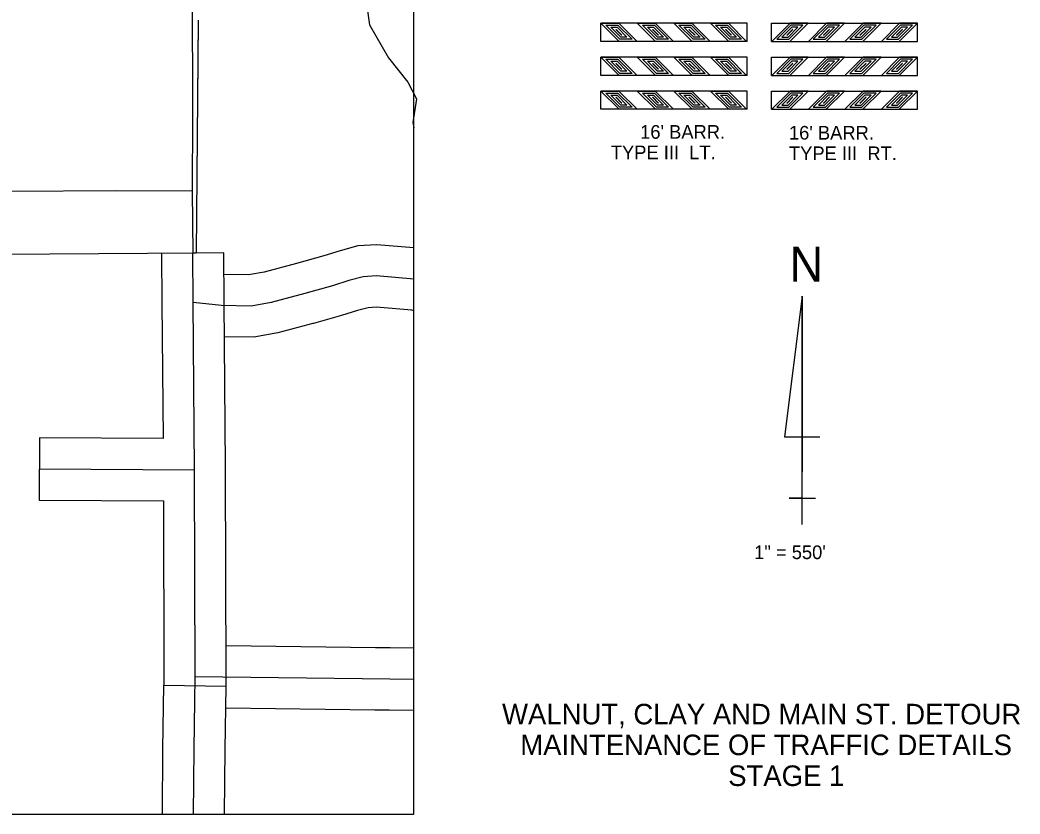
# Model space of a CAD drawing. Extents: x 988392 to 996681, y 1838707 to 1844440.
# Drawn here: x 994176 to 996584, y 1838707 to 1840620 of the extents above; entities that cross this region are included whole.
import ezdxf

# ---------------------------------------------------------------- set-up
doc = ezdxf.new("R2010")
doc.units = 0
for name, color, linetype in [('3', 7, 'Continuous'), ('63', 7, 'Continuous'), ('8', 7, 'Continuous'), ('G-ANNO-TEXT', 7, 'Continuous'), ('G-Border-Sheet', 7, 'Continuous'), ('Level 31', 7, 'Continuous'), ('Level 33', 7, 'Continuous'), ('Level 35', 7, 'Continuous'), ('Level 45', 7, 'Continuous'), ('Level 6', 7, 'Continuous')]:
    doc.layers.add(name, color=color, linetype=linetype)

msp = doc.modelspace()

# ---------------------------------------------------------------- linework, layer by layer
at = {"layer": '3'}
for p, q in [((995927, 1840612.6), (995574.8, 1840612.6)), ((995574.8, 1840568.4), (995574.8, 1840612.6)), ((995927, 1840568.4), (995927, 1840612.6)), ((995985.8, 1840612.6), (996337.9, 1840612.6)), ((995985.8, 1840568.4), (995985.8, 1840612.6)), ((996337.9, 1840568.4), (996337.9, 1840612.6)), ((995575.1, 1840568.5), (995574.8, 1840568.8)), ((995927, 1840568.4), (995574.8, 1840568.4)), ((995985.8, 1840568.4), (996337.9, 1840568.4)), ((996337.7, 1840568.5), (996337.9, 1840568.8)), ((995927, 1840530.6), (995574.8, 1840530.6)), ((995574.8, 1840486.5), (995574.8, 1840530.6)), ((995574.8, 1840486.5), (995574.8, 1840530.6)), ((995927, 1840486.5), (995927, 1840530.6)), ((995985.8, 1840530.6), (996337.9, 1840530.6)), ((995985.8, 1840486.5), (995985.8, 1840530.6)), ((996337.9, 1840486.5), (996337.9, 1840530.6)), ((996337.9, 1840486.5), (996337.9, 1840530.6)), ((995927, 1840486.5), (995574.8, 1840486.5)), ((995985.8, 1840486.5), (996337.9, 1840486.5)), ((995927, 1840448.9), (995574.8, 1840448.9)), ((995574.8, 1840404.8), (995574.8, 1840448.9)), ((995927, 1840404.8), (995927, 1840448.9)), ((995985.8, 1840448.9), (996337.9, 1840448.9)), ((995985.8, 1840404.8), (995985.8, 1840448.9)), ((996337.9, 1840404.8), (996337.9, 1840448.9)), ((995927, 1840404.8), (995574.8, 1840404.8)), ((995985.8, 1840404.8), (996337.9, 1840404.8))]:
    msp.add_line(p, q, dxfattribs=at)
for points in [[(995574.8, 1840612.6), (995618.1, 1840612.5), (995662.1, 1840568.5), (995618.9, 1840568.5)], [(995586.9, 1840607.6), (995616.1, 1840607.5), (995650, 1840573.5), (995621, 1840573.5)], [(995637.9, 1840578.5), (995623.1, 1840578.5), (995599.1, 1840602.5), (995614, 1840602.5)], [(995611.2, 1840597.5), (995611.9, 1840597.5), (995625.9, 1840583.5), (995625.1, 1840583.5)], [(995662.8, 1840612.6), (995706.1, 1840612.5), (995750.1, 1840568.5), (995706.9, 1840568.5)], [(995674.9, 1840607.6), (995704.1, 1840607.5), (995738, 1840573.5), (995709, 1840573.5)], [(995725.9, 1840578.5), (995711.1, 1840578.5), (995687.1, 1840602.5), (995702, 1840602.5)], [(995699.2, 1840597.5), (995699.9, 1840597.5), (995713.9, 1840583.5), (995713.1, 1840583.5)], [(995750.8, 1840612.6), (995794.1, 1840612.5), (995838.1, 1840568.5), (995794.9, 1840568.5)], [(995762.9, 1840607.6), (995792.1, 1840607.5), (995826, 1840573.5), (995797, 1840573.5)], [(995813.9, 1840578.5), (995799.1, 1840578.5), (995775.1, 1840602.5), (995790, 1840602.5)], [(995787.2, 1840597.5), (995787.9, 1840597.5), (995801.9, 1840583.5), (995801.1, 1840583.5)], [(995838.8, 1840612.6), (995882.1, 1840612.5), (995926.1, 1840568.5), (995882.9, 1840568.5)], [(995850.9, 1840607.6), (995880.1, 1840607.5), (995914, 1840573.5), (995885, 1840573.5)], [(995901.9, 1840578.5), (995887.1, 1840578.5), (995863.1, 1840602.5), (995878, 1840602.5)], [(995875.2, 1840597.5), (995875.9, 1840597.5), (995889.9, 1840583.5), (995889.1, 1840583.5)], [(996073.9, 1840612.6), (996030.6, 1840612.5), (995986.7, 1840568.5), (996029.8, 1840568.5)], [(996061.8, 1840607.6), (996032.7, 1840607.5), (995998.7, 1840573.5), (996027.8, 1840573.5)], [(996010.8, 1840578.5), (996025.7, 1840578.5), (996049.7, 1840602.5), (996034.8, 1840602.5)], [(996037.6, 1840597.5), (996036.9, 1840597.5), (996022.9, 1840583.5), (996023.6, 1840583.5)], [(996161.9, 1840612.6), (996118.6, 1840612.5), (996074.7, 1840568.5), (996117.8, 1840568.5)], [(996149.8, 1840607.6), (996120.7, 1840607.5), (996086.7, 1840573.5), (996115.8, 1840573.5)], [(996098.8, 1840578.5), (996113.7, 1840578.5), (996137.7, 1840602.5), (996122.8, 1840602.5)], [(996125.6, 1840597.5), (996124.9, 1840597.5), (996110.9, 1840583.5), (996111.6, 1840583.5)], [(996249.9, 1840612.6), (996206.6, 1840612.5), (996162.7, 1840568.5), (996205.8, 1840568.5)], [(996237.8, 1840607.6), (996208.7, 1840607.5), (996174.7, 1840573.5), (996203.8, 1840573.5)], [(996186.8, 1840578.5), (996201.7, 1840578.5), (996225.7, 1840602.5), (996210.8, 1840602.5)], [(996213.6, 1840597.5), (996212.9, 1840597.5), (996198.9, 1840583.5), (996199.6, 1840583.5)], [(996337.9, 1840612.6), (996294.6, 1840612.5), (996250.7, 1840568.5), (996293.8, 1840568.5)], [(996325.8, 1840607.6), (996296.7, 1840607.5), (996262.7, 1840573.5), (996291.8, 1840573.5)], [(996274.8, 1840578.5), (996289.7, 1840578.5), (996313.7, 1840602.5), (996298.8, 1840602.5)], [(996301.6, 1840597.5), (996300.9, 1840597.5), (996286.9, 1840583.5), (996287.6, 1840583.5)], [(995574.8, 1840530.6), (995618.1, 1840530.5), (995662.1, 1840486.5), (995618.9, 1840486.5)], [(995586.9, 1840525.6), (995616.1, 1840525.5), (995650, 1840491.5), (995621, 1840491.5)], [(995662.8, 1840530.6), (995706.1, 1840530.5), (995750.1, 1840486.5), (995706.9, 1840486.5)], [(995662.8, 1840530.6), (995706.1, 1840530.5), (995750.1, 1840486.5), (995706.9, 1840486.5)], [(995674.9, 1840525.6), (995704.1, 1840525.5), (995738, 1840491.5), (995709, 1840491.5)], [(995750.8, 1840530.6), (995794.1, 1840530.5), (995838.1, 1840486.5), (995794.9, 1840486.5)], [(995762.9, 1840525.6), (995792.1, 1840525.5), (995826, 1840491.5), (995797, 1840491.5)], [(995838.8, 1840530.6), (995882.1, 1840530.5), (995926.1, 1840486.5), (995882.9, 1840486.5)], [(995850.9, 1840525.6), (995880.1, 1840525.5), (995914, 1840491.5), (995885, 1840491.5)], [(996073.9, 1840530.6), (996030.6, 1840530.5), (995986.7, 1840486.5), (996029.8, 1840486.5)], [(996061.8, 1840525.6), (996032.7, 1840525.5), (995998.7, 1840491.5), (996027.8, 1840491.5)], [(996161.9, 1840530.6), (996118.6, 1840530.5), (996074.7, 1840486.5), (996117.8, 1840486.5)], [(996149.8, 1840525.6), (996120.7, 1840525.5), (996086.7, 1840491.5), (996115.8, 1840491.5)], [(996249.9, 1840530.6), (996206.6, 1840530.5), (996162.7, 1840486.5), (996205.8, 1840486.5)], [(996237.8, 1840525.6), (996208.7, 1840525.5), (996174.7, 1840491.5), (996203.8, 1840491.5)], [(996337.9, 1840530.6), (996294.6, 1840530.5), (996250.7, 1840486.5), (996293.8, 1840486.5)], [(996325.8, 1840525.6), (996296.7, 1840525.5), (996262.7, 1840491.5), (996291.8, 1840491.5)], [(995637.9, 1840496.5), (995623.1, 1840496.5), (995599.1, 1840520.6), (995614, 1840520.5)], [(995611.2, 1840515.5), (995611.9, 1840515.5), (995625.9, 1840501.5), (995625.1, 1840501.5)], [(995725.9, 1840496.5), (995711.1, 1840496.5), (995687.1, 1840520.6), (995702, 1840520.5)], [(995699.2, 1840515.5), (995699.9, 1840515.5), (995713.9, 1840501.5), (995713.1, 1840501.5)], [(995813.9, 1840496.5), (995799.1, 1840496.5), (995775.1, 1840520.6), (995790, 1840520.5)], [(995787.2, 1840515.5), (995787.9, 1840515.5), (995801.9, 1840501.5), (995801.1, 1840501.5)], [(995901.9, 1840496.5), (995887.1, 1840496.5), (995863.1, 1840520.6), (995878, 1840520.5)], [(995875.2, 1840515.5), (995875.9, 1840515.5), (995889.9, 1840501.5), (995889.1, 1840501.5)], [(996010.8, 1840496.5), (996025.7, 1840496.5), (996049.7, 1840520.6), (996034.8, 1840520.5)], [(996037.6, 1840515.5), (996036.9, 1840515.5), (996022.9, 1840501.5), (996023.6, 1840501.5)], [(996098.8, 1840496.5), (996113.7, 1840496.5), (996137.7, 1840520.6), (996122.8, 1840520.5)], [(996125.6, 1840515.5), (996124.9, 1840515.5), (996110.9, 1840501.5), (996111.6, 1840501.5)], [(996186.8, 1840496.5), (996201.7, 1840496.5), (996225.7, 1840520.6), (996210.8, 1840520.5)], [(996213.6, 1840515.5), (996212.9, 1840515.5), (996198.9, 1840501.5), (996199.6, 1840501.5)], [(996274.8, 1840496.5), (996289.7, 1840496.5), (996313.7, 1840520.6), (996298.8, 1840520.5)], [(996301.6, 1840515.5), (996300.9, 1840515.5), (996286.9, 1840501.5), (996287.6, 1840501.5)], [(995574.8, 1840448.9), (995618.1, 1840448.8), (995662.1, 1840404.8), (995618.9, 1840404.8)], [(995586.9, 1840443.9), (995616.1, 1840443.8), (995650, 1840409.8), (995621, 1840409.8)], [(995637.9, 1840414.8), (995623.1, 1840414.8), (995599.1, 1840438.8), (995614, 1840438.8)], [(995611.2, 1840433.8), (995611.9, 1840433.8), (995625.9, 1840419.8), (995625.1, 1840419.8)], [(995662.8, 1840448.9), (995706.1, 1840448.8), (995750.1, 1840404.8), (995706.9, 1840404.8)], [(995662.8, 1840448.9), (995706.1, 1840448.8), (995750.1, 1840404.8), (995706.9, 1840404.8)], [(995674.9, 1840443.9), (995704.1, 1840443.8), (995738, 1840409.8), (995709, 1840409.8)], [(995725.9, 1840414.8), (995711.1, 1840414.8), (995687.1, 1840438.8), (995702, 1840438.8)], [(995699.2, 1840433.8), (995699.9, 1840433.8), (995713.9, 1840419.8), (995713.1, 1840419.8)], [(995750.8, 1840448.9), (995794.1, 1840448.8), (995838.1, 1840404.8), (995794.9, 1840404.8)], [(995762.9, 1840443.9), (995792.1, 1840443.8), (995826, 1840409.8), (995797, 1840409.8)], [(995813.9, 1840414.8), (995799.1, 1840414.8), (995775.1, 1840438.8), (995790, 1840438.8)], [(995787.2, 1840433.8), (995787.9, 1840433.8), (995801.9, 1840419.8), (995801.1, 1840419.8)], [(995838.8, 1840448.9), (995882.1, 1840448.8), (995926.1, 1840404.8), (995882.9, 1840404.8)], [(995850.9, 1840443.9), (995880.1, 1840443.8), (995914, 1840409.8), (995885, 1840409.8)], [(995901.9, 1840414.8), (995887.1, 1840414.8), (995863.1, 1840438.8), (995878, 1840438.8)], [(995875.2, 1840433.8), (995875.9, 1840433.8), (995889.9, 1840419.8), (995889.1, 1840419.8)], [(996073.9, 1840448.9), (996030.6, 1840448.8), (995986.7, 1840404.8), (996029.8, 1840404.8)], [(996061.8, 1840443.9), (996032.7, 1840443.8), (995998.7, 1840409.8), (996027.8, 1840409.8)], [(996010.8, 1840414.8), (996025.7, 1840414.8), (996049.7, 1840438.8), (996034.8, 1840438.8)], [(996037.6, 1840433.8), (996036.9, 1840433.8), (996022.9, 1840419.8), (996023.6, 1840419.8)], [(996161.9, 1840448.9), (996118.6, 1840448.8), (996074.7, 1840404.8), (996117.8, 1840404.8)], [(996149.8, 1840443.9), (996120.7, 1840443.8), (996086.7, 1840409.8), (996115.8, 1840409.8)], [(996098.8, 1840414.8), (996113.7, 1840414.8), (996137.7, 1840438.8), (996122.8, 1840438.8)], [(996125.6, 1840433.8), (996124.9, 1840433.8), (996110.9, 1840419.8), (996111.6, 1840419.8)], [(996249.9, 1840448.9), (996206.6, 1840448.8), (996162.7, 1840404.8), (996205.8, 1840404.8)], [(996237.8, 1840443.9), (996208.7, 1840443.8), (996174.7, 1840409.8), (996203.8, 1840409.8)], [(996186.8, 1840414.8), (996201.7, 1840414.8), (996225.7, 1840438.8), (996210.8, 1840438.8)], [(996213.6, 1840433.8), (996212.9, 1840433.8), (996198.9, 1840419.8), (996199.6, 1840419.8)], [(996337.9, 1840448.9), (996294.6, 1840448.8), (996250.7, 1840404.8), (996293.8, 1840404.8)], [(996325.8, 1840443.9), (996296.7, 1840443.8), (996262.7, 1840409.8), (996291.8, 1840409.8)], [(996274.8, 1840414.8), (996289.7, 1840414.8), (996313.7, 1840438.8), (996298.8, 1840438.8)], [(996301.6, 1840433.8), (996300.9, 1840433.8), (996286.9, 1840419.8), (996287.6, 1840419.8)]]:
    msp.add_lwpolyline(points, close=True, dxfattribs=at)
at = {"layer": '63'}
for p, q in [((996060, 1839954.3), (996017.6, 1839615.8)), ((996060, 1839404.3), (996060, 1839954.3)), ((996060, 1839954.3), (996060, 1839531.2)), ((996017.6, 1839615.8), (996102.3, 1839615.8)), ((996060, 1839404.3), (996060, 1839531.2)), ((996060, 1839467.7), (996028.2, 1839467.7)), ((996028.2, 1839467.7), (996091.7, 1839467.7)), ((996060, 1839404.3), (996060, 1839467.7))]:
    msp.add_line(p, q, dxfattribs=at)
at = {"layer": 'G-Border-Sheet'}
msp.add_lwpolyline([(995124.8, 1844439.6), (989844.9, 1844439.6), (989844.9, 1838706.8), (995124.8, 1838706.8)], close=True, dxfattribs=at)
at = {"layer": 'Level 31'}
for p, q in [((994223.1, 1839613.2), (994222.3, 1839463.2)), ((994522.4, 1839017.2), (994672.4, 1839015.1))]:
    msp.add_line(p, q, dxfattribs=at)
for points in [[(994671.3, 1839544.7), (994668, 1839940.1), (994667, 1840058.9), (994517, 1840057.7)], [(994517, 1840057.7), (994518, 1839938.9), (994520.7, 1839611.7)], [(994593, 1839939.5), (994592, 1840058.3)], [(994597.7, 1839037.6), (994596.4, 1839536.4), (994593, 1839939.5)], [(994520.7, 1839611.7), (994223.1, 1839613.2)], [(994222.7, 1839538.2), (994596.4, 1839536.4)], [(994672.4, 1839015.1), (994672.7, 1839037.2), (994671.4, 1839536.8), (994671.3, 1839544.7)], [(994222.3, 1839463.2), (994521.6, 1839461.7)], [(994521.6, 1839461.7), (994522.7, 1839038), (994522.4, 1839017.2)], [(995032.5, 1839107.4), (994672.5, 1839111.7)], [(995124.8, 1839106.2), (995067.3, 1839107), (995032.5, 1839107.4)], [(994593.9, 1838706.8), (994595.3, 1838863.1), (994597.7, 1839037.6)], [(995124.8, 1839031.2), (995066.4, 1839032), (994597.7, 1839037.6)], [(994518.9, 1838706.8), (994520.3, 1838864), (994522.4, 1839017.2)], [(994668.9, 1838706.8), (994670.3, 1838862.3), (994672.4, 1839015.1)], [(995030.7, 1838957.4), (994671.7, 1838961.7)], [(995124.8, 1838956.2), (995065.4, 1838957), (995030.7, 1838957.4)]]:
    msp.add_lwpolyline(points, dxfattribs=at)
at = {"layer": 'Level 33'}
for points in [[(994590.8, 1840695.9), (994591.8, 1840389.2), (994590.7, 1840207.6), (994592, 1840058.3)], [(994590.7, 1840207.6), (994406.9, 1840208.7), (994153.7, 1840206.5), (993966.9, 1840206.5), (993845.7, 1840204.2), (993757.2, 1840200.9), (993707, 1840205.3), (993681, 1840209.8), (993653, 1840223.3), (993625, 1840251.3), (993597.2, 1840282.6)]]:
    msp.add_lwpolyline(points, dxfattribs=at)
at = {"layer": 'Level 35'}
msp.add_lwpolyline([(995074, 1840846.3), (995036.8, 1840786.5), (995019.5, 1840742.6), (995007.6, 1840681.5), (995018.2, 1840608.4), (995063.3, 1840528.6), (995109.8, 1840470.1), (995131.1, 1840430.3), (995121.8, 1840373.1), (995124.8, 1840360.1)], dxfattribs=at)
at = {"layer": 'Level 45'}
for points in [[(995124.8, 1840070.8), (995035.5, 1840078.6), (994989.8, 1840075.5), (994947.4, 1840064.2), (994907.5, 1840051.6), (994842.4, 1840033.2)], [(994842.4, 1840033.2), (994842.1, 1840033.1), (994764.4, 1840012.7), (994726.7, 1840005.9), (994667.5, 1840006.8)], [(995124.8, 1839995.5), (995034.8, 1840003.4), (995002.2, 1840001.2), (994968.4, 1839992.2), (994929, 1839979.8), (994861.9, 1839960.8), (994780.7, 1839939.5), (994732.9, 1839930.8), (994661.2, 1839931.9), (994593, 1839939.5)], [(995124.8, 1839919.5), (995119.8, 1839920.7), (995034.1, 1839928.2), (995014.5, 1839926.8), (994989.3, 1839920.1), (994950.4, 1839907.9), (994883.2, 1839888.9)], [(994883.2, 1839888.9), (994881.6, 1839888.4), (994797, 1839866.2), (994739.1, 1839855.7), (994668.7, 1839856.7)]]:
    msp.add_lwpolyline(points, dxfattribs=at)
at = {"layer": 'Level 6'}
for points in [[(994605.4, 1840619.7), (994600.2, 1840058.2), (993073.2, 1840048), (992681.4, 1839592.2), (991963.8, 1838786.5), (991963.2, 1838706.8)], [(994605.4, 1840619.6), (994600.2, 1840058.2), (993073.2, 1840048), (992681.4, 1839592.2), (991963.8, 1838786.5), (991963.2, 1838706.8)], [(994605.3, 1840618.1), (994600.2, 1840058.2), (993073.2, 1840048), (992681.4, 1839592.2), (991963.8, 1838786.5), (991963.2, 1838706.8)]]:
    msp.add_lwpolyline(points, dxfattribs=at)

# ---------------------------------------------------------------- texts
at = {"layer": '63'}
msp.add_text('N', height=84.6, dxfattribs=at).set_placement((996029, 1839989.5))
at = {"layer": '8'}
msp.add_text("16' BARR.", height=33, dxfattribs=at).set_placement((995669.6, 1840333.9))
for s, rotation, p in [("16' BARR.", 360, (996028, 1840331.8)), ('TYPE III  LT.', 360, (995599, 1840284.4)), ('TYPE III  RT.', 360, (996028, 1840282.3)), ('1" = 550\'', 0, (995944.2, 1839321))]:
    msp.add_text(s, height=33, rotation=rotation, dxfattribs=at).set_placement(p)
at = {"layer": 'G-ANNO-TEXT'}
for s, p in [('WALNUT, CLAY AND MAIN ST. DETOUR', (995337.1, 1838922.8)), ('MAINTENANCE OF TRAFFIC DETAILS', (995380.9, 1838848.6)), (' STAGE 1', (995863.3, 1838774.3))]:
    msp.add_text(s, height=49.5, dxfattribs=at).set_placement(p)

doc.saveas('drawing.dxf')
